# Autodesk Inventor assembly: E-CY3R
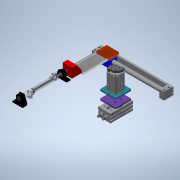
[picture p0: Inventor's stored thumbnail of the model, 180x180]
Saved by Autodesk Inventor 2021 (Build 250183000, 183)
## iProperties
Created: 2021-01
Part Number: E-CY3R
Material: Genérico
Document SubType Name: Assembly
Designer: ATOUZA
Author: ATOUZA
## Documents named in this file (10)
- D:\01 Paralaia\Grupos de Traballo\GT Maquetas\CAD 3D\E_Alimentación\Estación Alimentación.iam
- D:\01 Paralaia\Grupos de Traballo\GT Maquetas\CAD 3D\E_Alimentación\SMC_JP_CY3R15200M9B000\CY3R15-200-M9B(0_0_0).iam
- D:\01 Paralaia\Grupos de Traballo\GT Maquetas\CAD 3D\E_Alimentación\SoportePieza-CY3R.ipt
- D:\01 Paralaia\Grupos de Traballo\GT Maquetas\CAD 3D\E_Alimentación\PuenteTranporte.ipt
- D:\01 Paralaia\Grupos de Traballo\GT Maquetas\CAD 3D\E_Alimentación\SMC_JP_CD85N16100MBM9B000\CD85N16-100M-B-M9B(0__0_0).iam
- D:\01 Paralaia\Grupos de Traballo\GT Maquetas\CAD 3D\E_Alimentación\EmpujadorCilindro.ipt
- D:\01 Paralaia\Grupos de Traballo\GT Maquetas\CAD 3D\E_Alimentación\SMC_JP_MSQXB10AM9B0\MSQXB10A-M9B(0).iam
- D:\01 Paralaia\Grupos de Traballo\GT Maquetas\CAD 3D\E_Alimentación\SMC_JP_CDQMB2530M9B000\CDQMB25-30-M9B(0_0_0).iam
- D:\01 Paralaia\Grupos de Traballo\GT Maquetas\CAD 3D\E_Alimentación\Placa cilindro rotatorio.ipt
- D:\01 Paralaia\Grupos de Traballo\GT Maquetas\CAD 3D\E_Alimentación\Placa cilindro elevador.ipt
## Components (9 placed, 9 different names)
1. CY3R15-200-M9B(0_0_0):1 [sub-assembly] — Insertar:1, Insertar:2
2. SoportePieza-CY3R:1 — Insertar:1, Insertar:2
3. PuenteTranporte:1 — Coincidencia:1, Coincidencia:2, Coincidencia:3
4. CD85N16-100M-B-M9B(0__0_0):1 [sub-assembly] — Ángulo:1, Coincidencia:3, Insertar:3
5. EmpujadorCilindro:1 — Ángulo:1, Coincidencia:1, Coincidencia:2, Insertar:3
6. MSQXB10A-M9B(0):1 [sub-assembly] — Nivelación:1
7. CDQMB25-30-M9B(0_0_0):1 [sub-assembly] — Nivelación:3
8. Placa cilindro rotatorio:1 — Nivelación:1, Nivelación:4, Nivelación:5
9. Placa cilindro elevador:1 — Nivelación:3, Nivelación:4, Nivelación:5
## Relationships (11: Flush 4, Insert 3, Mate 3, Angle 1)
- Insertar:1: CY3R15-200-M9B(0_0_0):1 ↔ SoportePieza-CY3R:1
- Insertar:2: CY3R15-200-M9B(0_0_0):1 ↔ SoportePieza-CY3R:1
- Ángulo:1 [Angle]: CD85N16-100M-B-M9B(0__0_0):1 ↔ EmpujadorCilindro:1
- Coincidencia:1 [Mate]: PuenteTranporte:1 ↔ EmpujadorCilindro:1
- Coincidencia:2 [Mate]: PuenteTranporte:1 ↔ EmpujadorCilindro:1
- Coincidencia:3 [Mate]: PuenteTranporte:1 ↔ CD85N16-100M-B-M9B(0__0_0):1
- Insertar:3: CD85N16-100M-B-M9B(0__0_0):1 ↔ EmpujadorCilindro:1
- Nivelación:1 [Flush]: MSQXB10A-M9B(0):1 ↔ Placa cilindro rotatorio:1
- Nivelación:3 [Flush]: CDQMB25-30-M9B(0_0_0):1 ↔ Placa cilindro elevador:1
- Nivelación:4 [Flush]: Placa cilindro rotatorio:1 ↔ Placa cilindro elevador:1
- Nivelación:5 [Flush]: Placa cilindro rotatorio:1 ↔ Placa cilindro elevador:1
